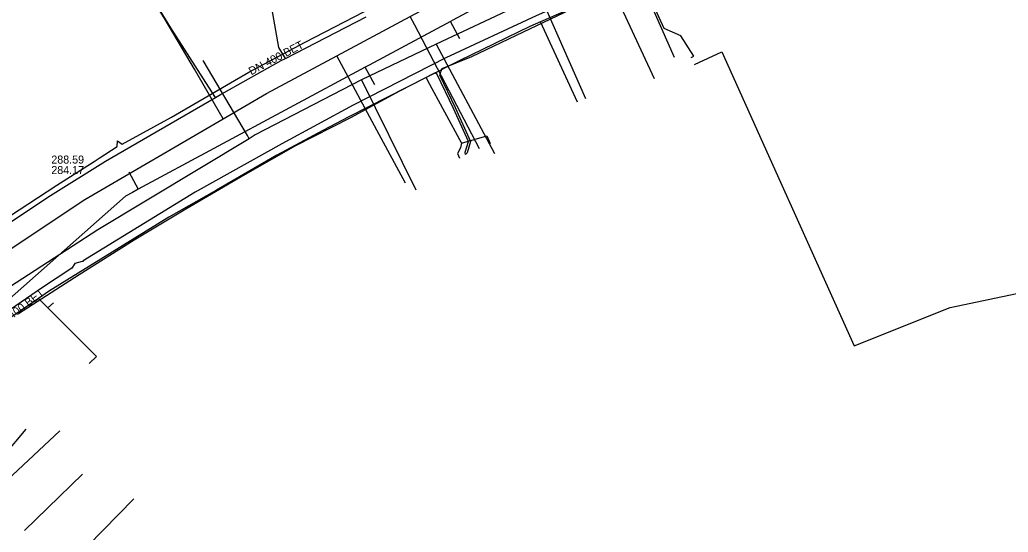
# Model space of a CAD drawing. Extents: x -600309 to -598967, y -1161267 to -1160292.
# Drawn here: x -599944.1 to -599845.4, y -1160418.4 to -1160367.2 of the extents above; entities that cross this region are included whole.
import ezdxf

# ---------------------------------------------------------------- set-up
doc = ezdxf.new("R2010")
doc.units = 0
for name, color, linetype in [('Vrstva 12', 7, 'Continuous'), ('Vrstva 13', 7, 'Continuous'), ('Vrstva 16', 7, 'Continuous'), ('Vrstva 42', 7, 'Continuous'), ('Vrstva 55', 7, 'Continuous'), ('Vrstva 9', 7, 'Continuous')]:
    doc.layers.add(name, color=color, linetype=linetype)

msp = doc.modelspace()

# ---------------------------------------------------------------- linework, layer by layer
at = {"layer": 'Vrstva 12'}
for points in [[(-599917.59, -1160371.07), (-599918.24, -1160369.97), (-599920.26, -1160358.61), (-599920.93, -1160357.15), (-599919.16, -1160355.17)], [(-599924.59, -1160374.96), (-599925.25, -1160373.92), (-599929.03, -1160368.01), (-599932.34, -1160362.59)], [(-599882.05, -1160363.01), (-599884.96, -1160364.26), (-599892.11, -1160367.4)], [(-599877.04, -1160370.97), (-599876.77, -1160370.84), (-599878.07, -1160368.8), (-599879.75, -1160368.05), (-599882.05, -1160363.01)], [(-599917.59, -1160371.07), (-599909.51, -1160366.89)], [(-599892.11, -1160367.4), (-599893.18, -1160367.87), (-599900.24, -1160371.3), (-599903.53, -1160372.96)], [(-599888.41, -1160375.44), (-599892.11, -1160367.4)], [(-599924.07, -1160374.67), (-599923.7, -1160374.47), (-599918.02, -1160371.27), (-599917.59, -1160371.07)], [(-599903.53, -1160372.96), (-599911.27, -1160376.88), (-599913.86, -1160378.25), (-599918.45, -1160380.73), (-599924.48, -1160384.21), (-599929.24, -1160386.91), (-599938.3, -1160392.53), (-599941.25, -1160394.37), (-599942.26, -1160395.06)], [(-599903.53, -1160372.96), (-599903.38, -1160373.25), (-599900.01, -1160379.51)], [(-599963.61, -1160400.2), (-599952.22, -1160392.16), (-599941.05, -1160384.74), (-599935.56, -1160381.31), (-599924.59, -1160374.96)], [(-599924.59, -1160374.96), (-599924.07, -1160374.67)], [(-599900.01, -1160379.51), (-599897.48, -1160378.78), (-599897.12, -1160379.57)], [(-599900.01, -1160379.51), (-599900.11, -1160380), (-599900.4, -1160380.57), (-599900.19, -1160381.02)], [(-599942.26, -1160395.06), (-599951.77, -1160401.55), (-599953.71, -1160403.62), (-599955.67, -1160406.08), (-599955.87, -1160406.32)], [(-599942.26, -1160395.06), (-599941.32, -1160395.99)], [(-599941.32, -1160395.99), (-599940.78, -1160395.5)], [(-599941.32, -1160395.99), (-599936.47, -1160400.85), (-599937.2, -1160401.54)]]:
    msp.add_lwpolyline(points, dxfattribs=at)
at = {"layer": 'Vrstva 13'}
for p, q in [((-599886.19, -1160361.31), (-599880.73, -1160373.057)), ((-599902.54, -1160369.63), (-599896.713, -1160380.543)), ((-599909.986, -1160373.19), (-599904.544, -1160384.194))]:
    msp.add_line(p, q, dxfattribs=at)
for points in [[(-599894.43, -1160365.84), (-599902.54, -1160369.63), (-599909.986, -1160373.19), (-599920.605, -1160378.688), (-599921.207, -1160379.075), (-599936.343, -1160388.199), (-599960.18, -1160403.66)], [(-599876.7, -1160371.67), (-599873.99, -1160370.38), (-599860.75, -1160399.8), (-599851.16, -1160395.95), (-599826.3, -1160390.71), (-599823.66, -1160402.03), (-599796.32, -1160394.8), (-599791.82, -1160405.69), (-599791.12, -1160410.51), (-599790.74, -1160413.61), (-599788.17, -1160413.06), (-599788.05, -1160413.74)], [(-599921.207, -1160379.075), (-599921.364, -1160378.774), (-599925.809, -1160371.261)], [(-599951.54, -1160419.4), (-599951.31, -1160419.14), (-599948.03, -1160415.65), (-599940.131, -1160408.289)], [(-599943.79, -1160426.66), (-599943.59, -1160426.44), (-599940.4, -1160422.91), (-599932.725, -1160415.07)]]:
    msp.add_lwpolyline(points, dxfattribs=at)
at = {"layer": 'Vrstva 16'}
for points in [[(-599963.47, -1160402.36), (-599961.01, -1160400.72), (-599937.64, -1160385.15), (-599923.8, -1160377.08), (-599919.49, -1160374.56), (-599912.45, -1160370.78), (-599905.14, -1160366.86), (-599900.61, -1160364.43), (-599893.63, -1160361.35), (-599891.35, -1160360.35), (-599884.67, -1160357.41), (-599873.32, -1160353), (-599871.361, -1160352.261), (-599865.52, -1160350.14), (-599865.3, -1160350.05), (-599864.88, -1160349.89), (-599860.27, -1160348.08), (-599856.17, -1160346.52), (-599819.83, -1160335.69), (-599819.46, -1160335.48), (-599819.06, -1160335.44)], [(-599878.7, -1160370.96), (-599884.27, -1160358.32), (-599884.67, -1160357.41)], [(-599923.8, -1160377.08), (-599926.69, -1160372.14), (-599929.59, -1160367.17), (-599933.87, -1160360.24), (-599934.22, -1160360.44)], [(-599893.63, -1160361.35), (-599887.59, -1160375.06)], [(-599898.19, -1160380.08), (-599904.67, -1160367.74), (-599905.14, -1160366.86)], [(-599905.6, -1160383.54), (-599908.45, -1160378.23), (-599911.98, -1160371.66), (-599912.45, -1160370.78)], [(-599950.21, -1160416.11), (-599943.49, -1160408.12)]]:
    msp.add_lwpolyline(points, dxfattribs=at)
at = {"layer": 'Vrstva 42'}
for points in [[(-599951.47, -1160402), (-599951.968, -1160401.459), (-599952.156, -1160401.256), (-599952.65, -1160400.72), (-599956.53, -1160395.68), (-599956.78, -1160395.23), (-599956.77, -1160394.8), (-599956.65, -1160394.38), (-599951.72, -1160391.08), (-599946.17, -1160387.45), (-599940.44, -1160383.74), (-599936.705, -1160381.356), (-599936.21, -1160381.04), (-599934.41, -1160379.87), (-599934.37, -1160379.3), (-599933.9, -1160379.61), (-599928.97, -1160376.92), (-599921.24, -1160372.43), (-599915.61, -1160369.42), (-599907.76, -1160365.37), (-599902.03, -1160362.65), (-599901.43, -1160361.97), (-599899.98, -1160359.11), (-599899.98, -1160359.02)], [(-599889.143, -1160366.194), (-599893.83, -1160368.44), (-599898.99, -1160370.89), (-599901.97, -1160372.09), (-599902.183, -1160372.687), (-599900.619, -1160375.968), (-599899.093, -1160379.353), (-599899.436, -1160380.488), (-599899.59, -1160380.65), (-599899.628, -1160380.43), (-599899.307, -1160379.367), (-599900.801, -1160376.052), (-599902.416, -1160372.662), (-599902.63, -1160372.48), (-599906.19, -1160374.34), (-599911.08, -1160377), (-599916.57, -1160379.78), (-599921.6, -1160382.65), (-599927.53, -1160386.11), (-599932.69, -1160389.22), (-599938.19, -1160392.68), (-599944.25, -1160396.58)], [(-599943.675, -1160418.232), (-599937.868, -1160412.606)]]:
    msp.add_lwpolyline(points, dxfattribs=at)
at = {"layer": 'Vrstva 55'}
for points in [[(-599809.865, -1160349.004), (-599810.294, -1160349.107), (-599811.806, -1160346.074), (-599814.468, -1160342.809), (-599816.783, -1160341.628), (-599819.505, -1160341.669), (-599822.182, -1160342.145), (-599830.471, -1160344.294), (-599836.894, -1160345.848), (-599836.599, -1160346.093), (-599836.894, -1160345.848), (-599851.222, -1160350.306), (-599864.791, -1160355.376), (-599879.298, -1160360.936), (-599892.528, -1160366.786), (-599901.555, -1160370.982), (-599910.824, -1160375.735), (-599917.939, -1160379.603), (-599926.621, -1160384.418), (-599937.814, -1160391.284), (-599937.803, -1160391.368)], [(-599937.803, -1160391.368), (-599937.909, -1160391.34), (-599938.649, -1160391.55), (-599938.929, -1160392.01), (-599941.87, -1160393.97), (-599950.337, -1160399.737), (-599951.75, -1160400.7), (-599954.74, -1160403.49), (-599955.932, -1160405.454), (-599956.716, -1160408.642), (-599954.706, -1160412.365), (-599952.94, -1160413.279), (-599952.575, -1160414.575)]]:
    msp.add_lwpolyline(points, dxfattribs=at)
at = {"layer": 'Vrstva 9'}
for p, q in [((-599900.159, -1160369.111), (-599901.107, -1160367.35)), ((-599908.665, -1160373.689), (-599909.613, -1160371.928)), ((-599933.243, -1160382.378), (-599932.295, -1160384.139))]:
    msp.add_line(p, q, dxfattribs=at)
for points in [[(-599892.187, -1160362.548), (-599894.306, -1160363.689), (-599894.776, -1160363.942), (-599900.866, -1160367.22), (-599901.107, -1160367.35), (-599909.231, -1160371.723), (-599909.613, -1160371.928), (-599932.295, -1160384.139), (-599932.856, -1160384.441), (-599933.56, -1160384.82)], [(-599933.56, -1160384.82), (-599946.673, -1160396.373), (-599946.688, -1160396.386), (-599946.811, -1160396.494), (-599958.64, -1160405.41)]]:
    msp.add_lwpolyline(points, dxfattribs=at)

# ---------------------------------------------------------------- texts
at = {"layer": 'Vrstva 12'}
for rotation, p in [(27.84575, (-599921.003, -1160372.746)), (37.00682, (-599946.403, -1160398.267))]:
    msp.add_text('DN 400 BET', height=0.8, rotation=rotation, dxfattribs=at).set_placement(p)
for s, p in [('288.59', (-599940.984, -1160381.563)), ('284.17', (-599940.984, -1160382.613))]:
    msp.add_text(s, height=0.8, dxfattribs=at).set_placement(p)

doc.saveas('drawing.dxf')
